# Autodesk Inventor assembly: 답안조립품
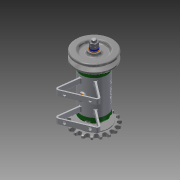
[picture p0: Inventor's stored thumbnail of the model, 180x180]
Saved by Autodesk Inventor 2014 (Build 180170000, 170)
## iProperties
Created: 2016-03
Part Number: 답안조립품
Document SubType Name: Assembly
Designer: user
Author: user
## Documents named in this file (16)
- D:\460308V1001\답안조립품.iam
- D:\460308V1001\본체.ipt
- D:\460308V1001\커버.ipt
- D:\460308V1001\베어링 15 x 32 x 9.ipt
- D:\460308V1001\오일 실 15 25 7.ipt
- D:\460308V1001\축.ipt
- D:\460308V1001\볼트 M4 x 12.ipt
- D:\460308V1001\키 3 x 3 x 12.ipt
- D:\460308V1001\V벨트풀리.ipt
- D:\460308V1001\스프로킷.ipt
- D:\460308V1001\와셔 8x17.ipt
- D:\460308V1001\스프링와셔 8.ipt
- D:\460308V1001\너트 M 8.ipt
- D:\460308V1001\볼트 M 6 x 8.ipt
- D:\460308V1001\와셔 6x11.5.ipt
- D:\460308V1001\니플 M 6 x 0.75.ipt
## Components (11 placed, 3 different names)
1. KS B 2023 6002 - 15 x 32 x 9:1 — Insert:1, Insert:7
2. KS B 2023 6002 - 15 x 32 x 9:2 — Insert:2
3. V벨트풀리:1 — Insert:10
4. ISO 4762 M4 x 12:1 — Insert:8
5. ISO 4762 M4 x 12:2
6. ISO 4762 M4 x 12:3
7. ISO 4762 M4 x 12:4
8. ISO 4762 M4 x 12:5 — Insert:9
9. ISO 4762 M4 x 12:6
10. ISO 4762 M4 x 12:7
11. ISO 4762 M4 x 12:8
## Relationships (6: Insert 6)
- Insert:1: KS B 2023 6002 - 15 x 32 x 9:1
- Insert:2: KS B 2023 6002 - 15 x 32 x 9:2
- Insert:7: KS B 2023 6002 - 15 x 32 x 9:1
- Insert:8: ISO 4762 M4 x 12:1
- Insert:9: ISO 4762 M4 x 12:5
- Insert:10: V벨트풀리:1
